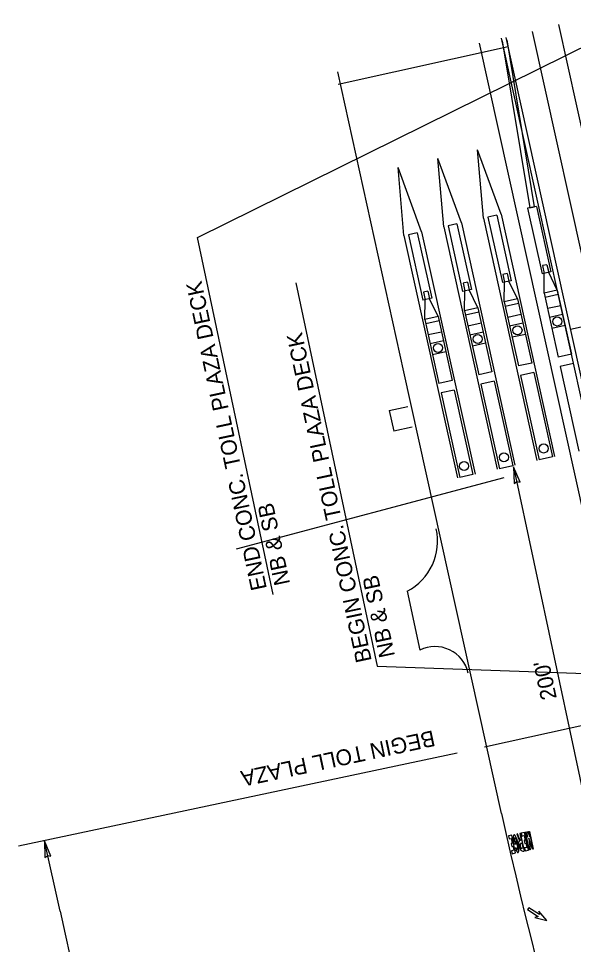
# Model space of a CAD drawing. Extents: x 578088 to 579220, y 1508751 to 1510398.
# Drawn here: x 578088 to 578333.4, y 1509907.9 to 1510317.1 of the extents above; entities that cross this region are included whole.
import ezdxf

# ---------------------------------------------------------------- set-up
doc = ezdxf.new("R2010")
doc.units = 0
for name, color, linetype in [('1', 7, 'Continuous'), ('18', 7, 'Continuous'), ('2', 7, 'Continuous'), ('20', 7, 'Continuous'), ('41', 7, 'Continuous'), ('52', 7, 'Continuous')]:
    doc.layers.add(name, color=color, linetype=linetype)

msp = doc.modelspace()

# ---------------------------------------------------------------- linework, layer by layer
at = {"layer": '1'}
msp.add_line((578559.88, 1509205.29), (578315.3, 1510311.37), dxfattribs=at)
at = {"layer": '18'}
for p, q in [((578471.12, 1509495.56), (578291.87, 1510306.19)), ((578301.41, 1510230.63), (578291.03, 1510259.06)), ((578293.6, 1510228.9), (578291.03, 1510259.06)), ((578283.84, 1510226.74), (578273.45, 1510255.17)), ((578276.03, 1510225.01), (578273.45, 1510255.17)), ((578266.26, 1510222.85), (578255.88, 1510251.28)), ((578258.45, 1510221.13), (578255.88, 1510251.28)), ((578317.03, 1510234.08), (578313.13, 1510233.22)), ((578313.13, 1510233.22), (578319.53, 1510204.25)), ((578317.03, 1510234.08), (578323.44, 1510205.11)), ((578293.6, 1510228.9), (578317.28, 1510121.82)), ((578299.46, 1510230.19), (578295.55, 1510229.33)), ((578295.55, 1510229.33), (578301.96, 1510200.36)), ((578299.46, 1510230.19), (578305.87, 1510201.22)), ((578301.41, 1510230.63), (578325.09, 1510123.54)), ((578276.03, 1510225.01), (578299.7, 1510117.93)), ((578281.88, 1510226.31), (578277.98, 1510225.45)), ((578277.98, 1510225.45), (578284.38, 1510196.47)), ((578281.88, 1510226.31), (578288.29, 1510197.34)), ((578283.84, 1510226.74), (578307.51, 1510119.66)), ((578258.45, 1510221.13), (578282.13, 1510114.04)), ((578264.31, 1510222.42), (578260.4, 1510221.56)), ((578260.4, 1510221.56), (578266.81, 1510192.59)), ((578264.31, 1510222.42), (578270.71, 1510193.45)), ((578266.26, 1510222.85), (578289.94, 1510115.77)), ((578321.71, 1510208.31), (578319.76, 1510207.88)), ((578319.76, 1510207.88), (578320.51, 1510204.46)), ((578321.71, 1510208.31), (578322.46, 1510204.9)), ((578304.13, 1510204.43), (578302.18, 1510203.99)), ((578302.18, 1510203.99), (578302.94, 1510200.58)), ((578304.13, 1510204.43), (578304.89, 1510201.01)), ((578323.44, 1510205.11), (578319.53, 1510204.25)), ((578320.39, 1510195.73), (578320.51, 1510204.46)), ((578326.25, 1510197.03), (578322.46, 1510204.9)), ((578286.56, 1510200.54), (578284.6, 1510200.11)), ((578284.6, 1510200.11), (578285.36, 1510196.69)), ((578286.56, 1510200.54), (578287.31, 1510197.12)), ((578305.87, 1510201.22), (578301.96, 1510200.36)), ((578302.82, 1510191.85), (578302.94, 1510200.58)), ((578308.68, 1510193.14), (578304.89, 1510201.01)), ((578268.98, 1510196.65), (578267.03, 1510196.22)), ((578267.03, 1510196.22), (578267.78, 1510192.8)), ((578268.98, 1510196.65), (578269.74, 1510193.24)), ((578288.29, 1510197.34), (578284.38, 1510196.47)), ((578285.24, 1510187.96), (578285.36, 1510196.69)), ((578291.1, 1510189.25), (578287.31, 1510197.12)), ((578326.25, 1510197.03), (578320.39, 1510195.73)), ((578320.39, 1510195.73), (578326.65, 1510167.42)), ((578326.25, 1510197.03), (578332.51, 1510168.71)), ((578270.71, 1510193.45), (578266.81, 1510192.59)), ((578267.67, 1510184.07), (578267.78, 1510192.8)), ((578273.53, 1510185.37), (578269.74, 1510193.24)), ((578308.68, 1510193.14), (578302.82, 1510191.85)), ((578302.82, 1510191.85), (578309.08, 1510163.53)), ((578309.11, 1510191.19), (578303.25, 1510189.89)), ((578308.68, 1510193.14), (578314.94, 1510164.83)), ((578326.68, 1510195.07), (578320.83, 1510193.78)), ((578291.1, 1510189.25), (578285.24, 1510187.96)), ((578285.24, 1510187.96), (578291.5, 1510159.64)), ((578291.53, 1510187.3), (578285.67, 1510186.01)), ((578291.1, 1510189.25), (578297.36, 1510160.94)), ((578327.76, 1510190.19), (578321.91, 1510188.9)), ((578273.53, 1510185.37), (578267.67, 1510184.07)), ((578267.67, 1510184.07), (578273.93, 1510155.76)), ((578273.96, 1510183.42), (578268.1, 1510182.12)), ((578273.53, 1510185.37), (578279.79, 1510157.05)), ((578310.19, 1510186.31), (578304.33, 1510185.01)), ((578328.63, 1510186.29), (578322.77, 1510184.99)), ((578292.61, 1510182.42), (578286.75, 1510181.12)), ((578311.05, 1510182.4), (578305.19, 1510181.11)), ((578329.71, 1510181.4), (578323.85, 1510180.11)), ((578275.04, 1510178.53), (578269.18, 1510177.24)), ((578293.48, 1510178.51), (578287.62, 1510177.22)), ((578312.13, 1510177.52), (578306.27, 1510176.22)), ((578275.9, 1510174.63), (578270.04, 1510173.33)), ((578294.56, 1510173.63), (578288.7, 1510172.34)), ((578276.98, 1510169.75), (578271.12, 1510168.45)), ((578332.51, 1510168.71), (578326.65, 1510167.42)), ((578314.94, 1510164.83), (578309.08, 1510163.53)), ((578333.43, 1510164.56), (578327.57, 1510163.27)), ((578327.57, 1510163.27), (578335.83, 1510125.92)), ((578297.36, 1510160.94), (578291.5, 1510159.64)), ((578315.86, 1510160.68), (578310, 1510159.38)), ((578310, 1510159.38), (578318.26, 1510122.03)), ((578315.86, 1510160.68), (578324.11, 1510123.33)), ((578279.79, 1510157.05), (578273.93, 1510155.76)), ((578298.28, 1510156.79), (578292.42, 1510155.49)), ((578292.42, 1510155.49), (578300.68, 1510118.15)), ((578298.28, 1510156.79), (578306.54, 1510119.44)), ((578280.7, 1510152.9), (578274.85, 1510151.61)), ((578274.85, 1510151.61), (578283.1, 1510114.26)), ((578280.7, 1510152.9), (578288.96, 1510115.55)), ((578324.11, 1510123.33), (578318.26, 1510122.03)), ((578306.54, 1510119.44), (578300.68, 1510118.15)), ((578288.96, 1510115.55), (578283.1, 1510114.26))]:
    msp.add_line(p, q, dxfattribs=at)
for centre in [(578326.24, 1510183.2), (578308.66, 1510179.31), (578291.09, 1510175.43), (578273.51, 1510171.54), (578320.21, 1510127.07), (578302.64, 1510123.19), (578285.06, 1510119.3)]:
    msp.add_circle(centre, 2, dxfattribs=at)
at = {"layer": '2'}
for p, q in [((578480.88, 1509497.72), (578301.64, 1510308.35)), ((578301.93, 1510307.24), (578314.1, 1510233.43)), ((578482.83, 1509498.15), (578303.59, 1510308.78)), ((578303.88, 1510307.67), (578316.06, 1510233.87)), ((578304.51, 1510304.62), (578229.33, 1510288)), ((578314.1, 1510233.43), (578316.06, 1510233.87)), ((578379.01, 1510190), (578332.14, 1510179.64)), ((578251.94, 1510143.85), (578253.95, 1510134.67)), ((578260.16, 1510145.47), (578251.97, 1510143.71)), ((578262.13, 1510136.54), (578253.93, 1510134.78)), ((578259.9, 1510064.06), (578265.45, 1510037.93)), ((578369.28, 1510011.7), (578294.1, 1509995.07))]:
    msp.add_line(p, q, dxfattribs=at)
for centre, radius, start, end in [((578248.34, 1510086.22), 25, 297.557, 12.4685), ((578272.22, 1510024.54), 15, 12.4685, 116.84)]:
    msp.add_arc(centre, radius, start, end, dxfattribs=at)
at = {"layer": '20'}
for p, q in [((578313.58, 1509957.79), (578313.9, 1509957.86)), ((578314.08, 1509955.51), (578313.58, 1509957.79)), ((578315.63, 1509950.05), (578313.9, 1509957.86)), ((578313.9, 1509957.86), (578315.63, 1509950.05)), ((578306.09, 1509956.13), (578304.63, 1509955.81)), ((578304.63, 1509955.81), (578304.91, 1509954.51)), ((578304.91, 1509954.51), (578305.89, 1509954.72)), ((578305.89, 1509954.72), (578306.36, 1509952.61)), ((578307.82, 1509948.32), (578306.09, 1509956.13)), ((578308.69, 1509956.71), (578308.37, 1509956.64)), ((578308.37, 1509956.64), (578309.51, 1509953.8)), ((578309.83, 1509953.89), (578308.69, 1509956.71)), ((578310, 1509957), (578309.67, 1509956.93)), ((578309.67, 1509956.93), (578310.32, 1509954)), ((578310.32, 1509954), (578309.83, 1509953.89)), ((578311.72, 1509949.19), (578310, 1509957)), ((578311.79, 1509957.39), (578310.32, 1509957.07)), ((578310.32, 1509957.07), (578310.61, 1509955.77)), ((578310.61, 1509955.77), (578311.59, 1509955.98)), ((578312.05, 1509953.87), (578311.57, 1509953.76)), ((578311.57, 1509953.76), (578311.85, 1509952.46)), ((578311.59, 1509955.98), (578312.05, 1509953.87)), ((578313.51, 1509949.58), (578311.79, 1509957.39)), ((578312.27, 1509957.52), (578312.59, 1509957.6)), ((578314, 1509949.69), (578312.27, 1509957.52)), ((578312.59, 1509957.6), (578313.1, 1509955.29)), ((578312.93, 1509957.64), (578313.25, 1509957.72)), ((578313.1, 1509955.29), (578312.93, 1509957.64)), ((578313.25, 1509957.72), (578314.08, 1509955.51)), ((578315.3, 1509949.98), (578313.7, 1509954.91)), ((578313.7, 1509954.91), (578314.33, 1509949.76)), ((578306.36, 1509952.61), (578305.87, 1509952.5)), ((578305.87, 1509952.5), (578306.16, 1509951.2)), ((578306.16, 1509951.2), (578306.65, 1509951.31)), ((578306.65, 1509951.31), (578307.04, 1509949.52)), ((578307.32, 1509953.5), (578307.61, 1509953.57)), ((578307.9, 1509952.27), (578307.32, 1509952.14)), ((578307.61, 1509953.57), (578307.9, 1509952.27)), ((578307.91, 1509949.77), (578307.94, 1509950.67)), ((578309.17, 1509952.99), (578309.87, 1509949.87)), ((578310.08, 1509952.58), (578310.61, 1509952.69)), ((578311.11, 1509950.42), (578310.56, 1509950.29)), ((578310.61, 1509952.69), (578311.11, 1509950.42)), ((578312.74, 1509950.78), (578311.76, 1509950.56)), ((578311.76, 1509950.56), (578312.05, 1509949.26)), ((578311.85, 1509952.46), (578312.34, 1509952.57)), ((578312.05, 1509949.26), (578313.51, 1509949.58)), ((578312.34, 1509952.57), (578312.74, 1509950.78)), ((578314.33, 1509949.76), (578314, 1509949.69)), ((578315.63, 1509950.05), (578315.3, 1509949.98)), ((578307.04, 1509949.52), (578306.06, 1509949.3)), ((578306.06, 1509949.3), (578306.35, 1509948)), ((578306.35, 1509948), (578307.82, 1509948.32)), ((578311.4, 1509949.11), (578311.72, 1509949.19)), ((578313.66, 1509924.13), (578313.12, 1509923.28)), ((578313.12, 1509923.28), (578317.82, 1509920.28)), ((578318.36, 1509921.12), (578313.66, 1509924.13)), ((578321.68, 1509918.42), (578318.15, 1509922.64)), ((578318.15, 1509922.64), (578318.36, 1509921.12)), ((578317.82, 1509920.28), (578316.35, 1509919.83)), ((578316.35, 1509919.83), (578321.68, 1509918.42))]:
    msp.add_line(p, q, dxfattribs=at)
for points in [[(578307.32, 1509952.14), (578306.8, 1509954.46)], [(578307.19, 1509954.09), (578307.32, 1509953.5)], [(578308.83, 1509950.84), (578308.07, 1509954.28)], [(578308.27, 1509954.78), (578309.22, 1509950.46)]]:
    msp.add_lwpolyline(points, dxfattribs=at)
for centre, major_axis, ratio, start_param, end_param in [((578308.01, 1509952.46), (0.86, -3.91), 0.225, 2.156482, 4.126703), ((578308.01, 1509952.46), (-0.58, 2.6), 0.225, 5.435123, 7.131247), ((578310.82, 1509951.72), (0.58, -2.6), 0.625, 3.662797, 4.068888), ((578308.01, 1509952.46), (0.86, -3.91), 0.225, 5.421015, 7.268296), ((578308.01, 1509952.46), (-0.58, 2.6), 0.225, 2.279423, 3.989655), ((578310.72, 1509951.52), (-0.27, 1.31), 0.625, 0.515234, 2.646405), ((578310.82, 1509951.72), (0.58, -2.6), 0.625, 5.35589, 6.283185)]:
    msp.add_ellipse(centre, major_axis=major_axis, ratio=ratio, start_param=start_param, end_param=end_param, dxfattribs=at)
at = {"layer": '41'}
for p, q in [((578374.47, 1510099.38), (578326.92, 1510314.41)), ((578258.43, 1510160.98), (578229.13, 1510293.53)), ((578301.62, 1509965.7), (578258.43, 1510160.98))]:
    msp.add_line(p, q, dxfattribs=at)
msp.add_arc((580335.96, 1510415.53), 2083.48, 192.46859, 200.71859, dxfattribs=at)
at = {"layer": '52'}
for p, q in [((578167.13, 1510220.3), (578363.2, 1510317.1)), ((578200.66, 1510062.58), (578167.13, 1510220.3)), ((578210.63, 1510200.27), (578246.65, 1510030.8)), ((578306.96, 1510119.01), (578349.08, 1509920.82)), ((578306.96, 1510119.01), (578307.15, 1510111.63)), ((578309.84, 1510112.22), (578306.96, 1510119.01)), ((578302.6, 1510114.15), (578184.21, 1510082.54)), ((578307.15, 1510111.63), (578308.4, 1510112.47)), ((578308.4, 1510112.47), (578309.84, 1510112.22)), ((578246.65, 1510030.8), (578427.87, 1510024.65)), ((578281.95, 1509992.49), (578087.97, 1509951.26)), ((578106.33, 1509922.52), (578099.44, 1509953.7)), ((578099.44, 1509953.7), (578099.64, 1509946.31)), ((578102.32, 1509946.91), (578099.44, 1509953.7)), ((578099.64, 1509946.31), (578100.89, 1509947.15)), ((578100.89, 1509947.15), (578102.32, 1509946.91))]:
    msp.add_line(p, q, dxfattribs=at)
msp.add_arc((580335.96, 1510415.53), 2283.48, 192.46859, 200.71859, dxfattribs=at)

# ---------------------------------------------------------------- texts
for s, rotation, p in [('END CONC. TOLL PLAZA DECK', 102, (578197.84, 1510065.17)), ('BEGIN CONC. TOLL PLAZA DECK', 102, (578244.24, 1510033.29)), ('NB & SB', 102, (578208.12, 1510067.36)), ('NB & SB', 102, (578254.51, 1510035.47)), ("200'", 102, (578326.08, 1510016.75)), ('BEGIN TOLL PLAZA', 192, (578271.29, 1510002.57))]:
    msp.add_text(s, height=7, rotation=rotation, dxfattribs=at).set_placement(p)

doc.saveas('drawing.dxf')
